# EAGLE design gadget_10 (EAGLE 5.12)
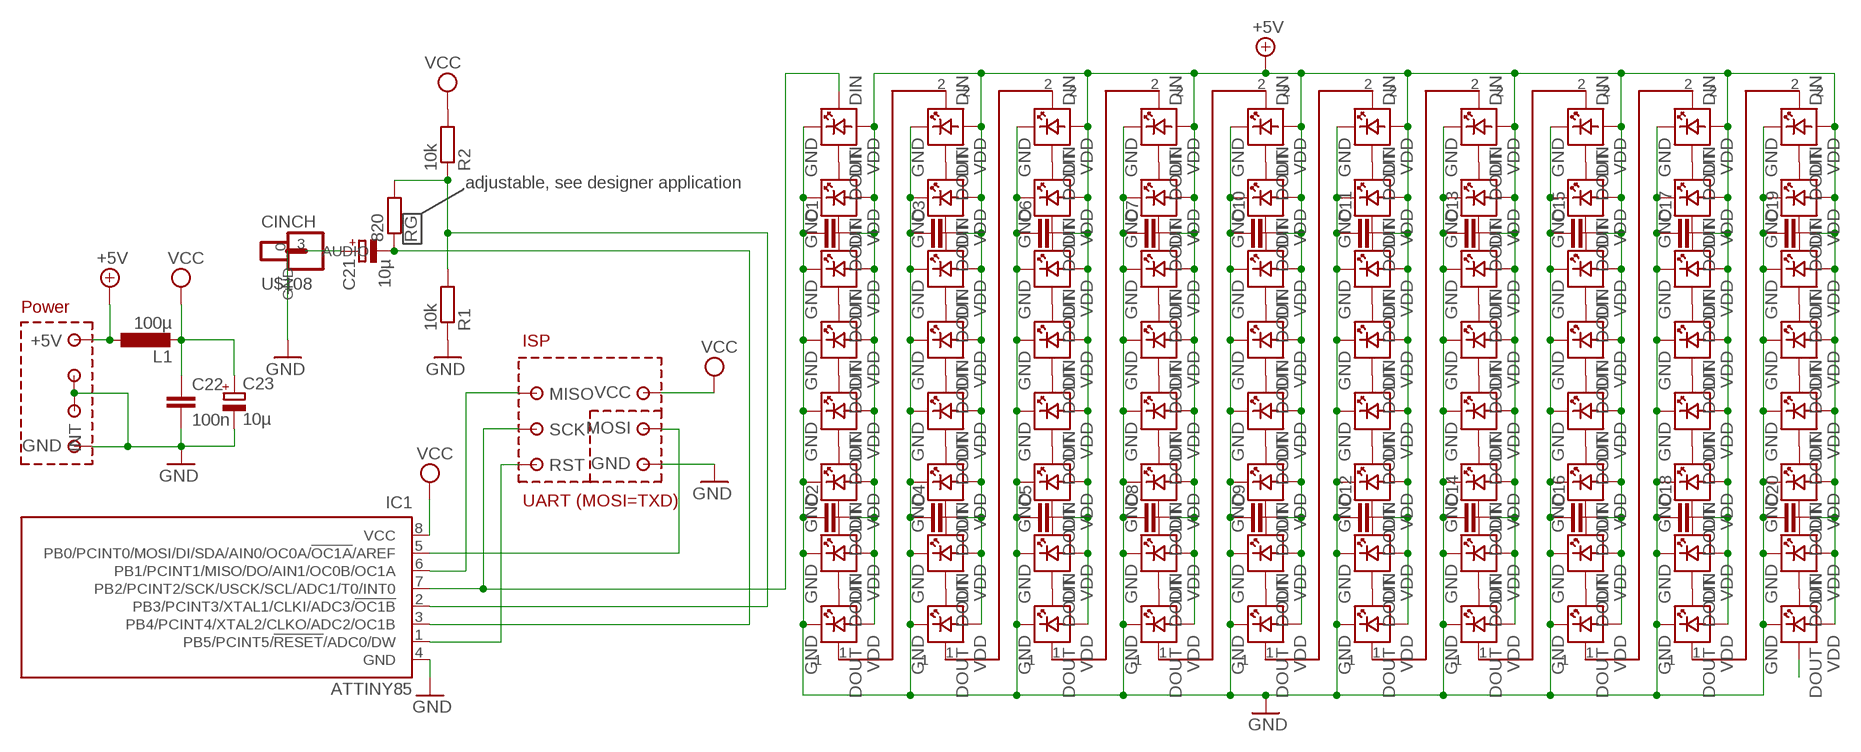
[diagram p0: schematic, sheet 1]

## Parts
C1  C-EU050-024X044  [C050-024X044]
C2  C-EU050-024X044  [C050-024X044]
C3  C-EU050-024X044  [C050-024X044]
C4  C-EU050-024X044  [C050-024X044]
C5  C-EU050-024X044  [C050-024X044]
C6  C-EU050-024X044  [C050-024X044]
C7  C-EU050-024X044  [C050-024X044]
C8  C-EU050-024X044  [C050-024X044]
C9  C-EU050-024X044  [C050-024X044]
C10  C-EU050-024X044  [C050-024X044]
C11  C-EU050-024X044  [C050-024X044]
C12  C-EU050-024X044  [C050-024X044]
C13  C-EU050-024X044  [C050-024X044]
C14  C-EU050-024X044  [C050-024X044]
C15  C-EU050-024X044  [C050-024X044]
C16  C-EU050-024X044  [C050-024X044]
C17  C-EU050-024X044  [C050-024X044]
C18  C-EU050-024X044  [C050-024X044]
C19  C-EU050-024X044  [C050-024X044]
C20  C-EU050-024X044  [C050-024X044]
C21  10µ  CPOL-EUE2.5-5  [E2,5-5]
C22  100n  C-EU025-024X044  [C025-024X044]
C23  10µ  CPOL-EUE2.5-5  [E2,5-5]
IC1  ATTINY85  TINY25/45/85  [DIL08]
L1  100µ  L-EU0207/12  [0207/12]
R1  10k  R-EU_0207/10  [0207/10]
R2  10k  R-EU_0207/7  [0207/7]
RG  820  R-EU_0207/7  [0207/7]
U$1  SPECIAL01  [SPECIAL01]
U$2  SPECIAL01  [SPECIAL01]
U$3  SPECIAL01  [SPECIAL01]
U$4  SPECIAL01  [SPECIAL01]
U$5  SPECIAL01  [SPECIAL01]
U$6  SPECIAL01  [SPECIAL01]
U$7  SPECIAL01  [SPECIAL01]
U$8  WS2812B  [WS2812B]
U$9  WS2812B  [WS2812B]
U$10  WS2812B  [WS2812B]
U$11  WS2812B  [WS2812B]
U$12  WS2812B  [WS2812B]
U$13  WS2812B  [WS2812B]
U$14  WS2812B  [WS2812B]
U$15  WS2812B  [WS2812B]
U$16  WS2812B  [WS2812B]
U$17  WS2812B  [WS2812B]
U$18  WS2812B  [WS2812B]
U$19  WS2812B  [WS2812B]
U$20  WS2812B  [WS2812B]
U$21  WS2812B  [WS2812B]
U$22  WS2812B  [WS2812B]
U$23  WS2812B  [WS2812B]
U$24  WS2812B  [WS2812B]
U$25  WS2812B  [WS2812B]
U$26  WS2812B  [WS2812B]
U$27  WS2812B  [WS2812B]
U$28  WS2812B  [WS2812B]
U$29  WS2812B  [WS2812B]
U$30  WS2812B  [WS2812B]
U$31  WS2812B  [WS2812B]
U$32  WS2812B  [WS2812B]
U$33  WS2812B  [WS2812B]
U$34  WS2812B  [WS2812B]
U$35  WS2812B  [WS2812B]
U$36  WS2812B  [WS2812B]
U$37  WS2812B  [WS2812B]
U$38  WS2812B  [WS2812B]
U$39  WS2812B  [WS2812B]
U$40  WS2812B  [WS2812B]
U$41  WS2812B  [WS2812B]
U$42  WS2812B  [WS2812B]
U$43  WS2812B  [WS2812B]
U$44  WS2812B  [WS2812B]
U$45  WS2812B  [WS2812B]
U$46  WS2812B  [WS2812B]
U$47  WS2812B  [WS2812B]
U$48  WS2812B  [WS2812B]
U$49  WS2812B  [WS2812B]
U$50  WS2812B  [WS2812B]
U$51  WS2812B  [WS2812B]
U$52  WS2812B  [WS2812B]
U$53  WS2812B  [WS2812B]
U$54  WS2812B  [WS2812B]
U$55  WS2812B  [WS2812B]
U$56  WS2812B  [WS2812B]
U$57  WS2812B  [WS2812B]
U$58  WS2812B  [WS2812B]
U$59  WS2812B  [WS2812B]
U$60  WS2812B  [WS2812B]
U$61  WS2812B  [WS2812B]
U$62  WS2812B  [WS2812B]
U$63  WS2812B  [WS2812B]
U$64  WS2812B  [WS2812B]
U$65  WS2812B  [WS2812B]
U$66  WS2812B  [WS2812B]
U$67  WS2812B  [WS2812B]
U$68  WS2812B  [WS2812B]
U$69  WS2812B  [WS2812B]
U$70  WS2812B  [WS2812B]
U$71  WS2812B  [WS2812B]
U$72  WS2812B  [WS2812B]
U$73  WS2812B  [WS2812B]
U$74  WS2812B  [WS2812B]
U$75  WS2812B  [WS2812B]
U$76  WS2812B  [WS2812B]
U$77  WS2812B  [WS2812B]
U$78  WS2812B  [WS2812B]
U$79  WS2812B  [WS2812B]
U$80  WS2812B  [WS2812B]
U$81  WS2812B  [WS2812B]
U$82  WS2812B  [WS2812B]
U$83  WS2812B  [WS2812B]
U$84  WS2812B  [WS2812B]
U$85  WS2812B  [WS2812B]
U$86  WS2812B  [WS2812B]
U$87  WS2812B  [WS2812B]
U$88  SPECIAL01  [SPECIAL01]
U$89  SPECIAL01  [SPECIAL01]
U$90  MOSI  PAD  [PAD]
U$91  MISO  PAD  [PAD]
U$92  SCK  PAD  [PAD]
U$93  RST  PAD  [PAD]
U$94  VCC  PAD  [PAD]
U$95  GND  PAD  [PAD]
U$96  GND  PAD  [PAD]
U$97  INT  PAD  [PAD]
U$98  PAD  [PAD]
U$108  CINCH  [CINCH]
VOLPWM_VCC1  +5V  PAD  [PAD]

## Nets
+5V: C1.2 C2.2 C3.2 C4.2 C5.2 C6.2 C7.2 C8.2 C9.2 C10.2 C11.2 C12.2 C13.2 C14.2 C15.2 C16.2 C17.2 C18.2 C19.2 C20.2 L1.1 U$8.1(VDD) U$9.1(VDD) U$10.1(VDD) U$11.1(VDD) U$12.1(VDD) U$13.1(VDD) U$14.1(VDD) U$15.1(VDD) U$16.1(VDD) U$17.1(VDD) U$18.1(VDD) U$19.1(VDD) U$20.1(VDD) U$21.1(VDD) U$22.1(VDD) U$23.1(VDD) U$24.1(VDD) U$25.1(VDD) U$26.1(VDD) U$27.1(VDD) U$28.1(VDD) U$29.1(VDD) U$30.1(VDD) U$31.1(VDD) U$32.1(VDD) U$33.1(VDD) U$34.1(VDD) U$35.1(VDD) U$36.1(VDD) U$37.1(VDD) U$38.1(VDD) U$39.1(VDD) U$40.1(VDD) U$41.1(VDD) U$42.1(VDD) U$43.1(VDD) U$44.1(VDD) U$45.1(VDD) U$46.1(VDD) U$47.1(VDD) U$48.1(VDD) U$49.1(VDD) U$50.1(VDD) U$51.1(VDD) U$52.1(VDD) U$53.1(VDD) U$54.1(VDD) U$55.1(VDD) U$56.1(VDD) U$57.1(VDD) U$58.1(VDD) U$59.1(VDD) U$60.1(VDD) U$61.1(VDD) U$62.1(VDD) U$63.1(VDD) U$64.1(VDD) U$65.1(VDD) U$66.1(VDD) U$67.1(VDD) U$68.1(VDD) U$69.1(VDD) U$70.1(VDD) U$71.1(VDD) U$72.1(VDD) U$73.1(VDD) U$74.1(VDD) U$75.1(VDD) U$76.1(VDD) U$77.1(VDD) U$78.1(VDD) U$79.1(VDD) U$80.1(VDD) U$81.1(VDD) U$82.1(VDD) U$83.1(VDD) U$84.1(VDD) U$85.1(VDD) U$86.1(VDD) U$87.1(VDD) VOLPWM_VCC1.P$1
GND: C1.1 C2.1 C3.1 C4.1 C5.1 C6.1 C7.1 C8.1 C9.1 C10.1 C11.1 C12.1 C13.1 C14.1 C15.1 C16.1 C17.1 C18.1 C19.1 C20.1 C22.2 C23.- IC1.4(GND) R1.1 U$8.3(GND) U$9.3(GND) U$10.3(GND) U$11.3(GND) U$12.3(GND) U$13.3(GND) U$14.3(GND) U$15.3(GND) U$16.3(GND) U$17.3(GND) U$18.3(GND) U$19.3(GND) U$20.3(GND) U$21.3(GND) U$22.3(GND) U$23.3(GND) U$24.3(GND) U$25.3(GND) U$26.3(GND) U$27.3(GND) U$28.3(GND) U$29.3(GND) U$30.3(GND) U$31.3(GND) U$32.3(GND) U$33.3(GND) U$34.3(GND) U$35.3(GND) U$36.3(GND) U$37.3(GND) U$38.3(GND) U$39.3(GND) U$40.3(GND) U$41.3(GND) U$42.3(GND) U$43.3(GND) U$44.3(GND) U$45.3(GND) U$46.3(GND) U$47.3(GND) U$48.3(GND) U$49.3(GND) U$50.3(GND) U$51.3(GND) U$52.3(GND) U$53.3(GND) U$54.3(GND) U$55.3(GND) U$56.3(GND) U$57.3(GND) U$58.3(GND) U$59.3(GND) U$60.3(GND) U$61.3(GND) U$62.3(GND) U$63.3(GND) U$64.3(GND) U$65.3(GND) U$66.3(GND) U$67.3(GND) U$68.3(GND) U$69.3(GND) U$70.3(GND) U$71.3(GND) U$72.3(GND) U$73.3(GND) U$74.3(GND) U$75.3(GND) U$76.3(GND) U$77.3(GND) U$78.3(GND) U$79.3(GND) U$80.3(GND) U$81.3(GND) U$82.3(GND) U$83.3(GND) U$84.3(GND) U$85.3(GND) U$86.3(GND) U$87.3(GND) U$95.P$1 U$96.P$1 U$97.P$1 U$98.P$1 U$108.0(GND)
N$1: U$1.1 U$15.2(DOUT)
N$4: U$1.2 U$16.4(DIN)
N$5: U$8.2(DOUT) U$9.4(DIN)
N$6: U$2.1 U$23.2(DOUT)
N$7: U$2.2 U$24.4(DIN)
N$8: U$3.1 U$31.2(DOUT)
N$9: U$9.2(DOUT) U$10.4(DIN)
N$10: U$10.2(DOUT) U$11.4(DIN)
N$11: U$11.2(DOUT) U$12.4(DIN)
N$12: U$12.2(DOUT) U$13.4(DIN)
N$13: U$13.2(DOUT) U$14.4(DIN)
N$14: U$14.2(DOUT) U$15.4(DIN)
N$15: U$16.2(DOUT) U$17.4(DIN)
N$16: U$17.2(DOUT) U$18.4(DIN)
N$17: U$18.2(DOUT) U$19.4(DIN)
N$18: U$19.2(DOUT) U$20.4(DIN)
N$19: U$20.2(DOUT) U$21.4(DIN)
N$20: U$21.2(DOUT) U$22.4(DIN)
N$21: U$22.2(DOUT) U$23.4(DIN)
N$22: U$24.2(DOUT) U$25.4(DIN)
N$23: U$25.2(DOUT) U$26.4(DIN)
N$24: U$26.2(DOUT) U$27.4(DIN)
N$25: U$27.2(DOUT) U$28.4(DIN)
N$26: U$28.2(DOUT) U$29.4(DIN)
N$27: U$29.2(DOUT) U$30.4(DIN)
N$28: U$30.2(DOUT) U$31.4(DIN)
N$29: U$32.2(DOUT) U$33.4(DIN)
N$30: U$33.2(DOUT) U$34.4(DIN)
N$31: U$34.2(DOUT) U$35.4(DIN)
N$32: U$35.2(DOUT) U$36.4(DIN)
N$33: U$36.2(DOUT) U$37.4(DIN)
N$34: U$37.2(DOUT) U$38.4(DIN)
N$35: U$38.2(DOUT) U$39.4(DIN)
N$36: U$40.2(DOUT) U$41.4(DIN)
N$37: U$41.2(DOUT) U$42.4(DIN)
N$38: U$42.2(DOUT) U$43.4(DIN)
N$39: U$43.2(DOUT) U$44.4(DIN)
N$40: U$44.2(DOUT) U$45.4(DIN)
N$41: U$45.2(DOUT) U$46.4(DIN)
N$42: U$46.2(DOUT) U$47.4(DIN)
N$43: U$48.2(DOUT) U$49.4(DIN)
N$44: U$49.2(DOUT) U$50.4(DIN)
N$45: U$50.2(DOUT) U$51.4(DIN)
N$46: U$51.2(DOUT) U$52.4(DIN)
N$47: U$52.2(DOUT) U$53.4(DIN)
N$48: U$53.2(DOUT) U$54.4(DIN)
N$49: U$54.2(DOUT) U$55.4(DIN)
N$50: U$56.2(DOUT) U$57.4(DIN)
N$51: U$57.2(DOUT) U$58.4(DIN)
N$52: U$58.2(DOUT) U$59.4(DIN)
N$53: U$59.2(DOUT) U$60.4(DIN)
N$54: U$60.2(DOUT) U$61.4(DIN)
N$55: U$61.2(DOUT) U$62.4(DIN)
N$56: U$62.2(DOUT) U$63.4(DIN)
N$57: U$64.2(DOUT) U$65.4(DIN)
N$58: U$65.2(DOUT) U$66.4(DIN)
N$59: U$66.2(DOUT) U$67.4(DIN)
N$60: U$67.2(DOUT) U$68.4(DIN)
N$61: U$68.2(DOUT) U$69.4(DIN)
N$62: U$69.2(DOUT) U$70.4(DIN)
N$63: U$70.2(DOUT) U$71.4(DIN)
N$64: U$72.2(DOUT) U$73.4(DIN)
N$65: U$73.2(DOUT) U$74.4(DIN)
N$66: U$74.2(DOUT) U$75.4(DIN)
N$67: U$75.2(DOUT) U$76.4(DIN)
N$68: U$76.2(DOUT) U$77.4(DIN)
N$69: U$77.2(DOUT) U$78.4(DIN)
N$70: U$78.2(DOUT) U$79.4(DIN)
N$71: U$80.2(DOUT) U$81.4(DIN)
N$72: U$81.2(DOUT) U$82.4(DIN)
N$73: U$82.2(DOUT) U$83.4(DIN)
N$74: U$83.2(DOUT) U$84.4(DIN)
N$75: U$84.2(DOUT) U$85.4(DIN)
N$76: U$85.2(DOUT) U$86.4(DIN)
N$77: U$86.2(DOUT) U$87.4(DIN)
N$78: U$3.2 U$32.4(DIN)
N$79: U$4.1 U$39.2(DOUT)
N$80: U$4.2 U$40.4(DIN)
N$81: U$5.1 U$47.2(DOUT)
N$82: U$5.2 U$48.4(DIN)
N$83: U$6.1 U$55.2(DOUT)
N$84: U$6.2 U$56.4(DIN)
N$85: U$7.1 U$63.2(DOUT)
N$86: U$7.2 U$64.4(DIN)
N$87: U$71.2(DOUT) U$88.1
N$88: U$72.4(DIN) U$88.2
N$89: U$79.2(DOUT) U$89.1
N$90: U$80.4(DIN) U$89.2
N$98: C21.+ U$108.3(AUDIO)
N$111: U$87.2(DOUT)
N$112: C21.- IC1.3(PB4/PCINT4/XTAL2/CLKO/ADC2/OC1B) RG.1
N$113: IC1.2(PB3/PCINT3/XTAL1/CLKI/ADC3/!OC1B!) R1.2 R2.1 RG.2
N$115: IC1.1(PB5/PCINT5/!RESET!/ADC0/DW) U$93.P$1
N$116: IC1.7(PB2/PCINT2/SCK/USCK/SCL/ADC1/T0/INT0) U$8.4(DIN) U$92.P$1
N$117: IC1.5(PB0/PCINT0/MOSI/DI/SDA/AIN0/OC0A/!OC1A!/AREF) U$90.P$1
N$118: IC1.6(PB1/PCINT1/MISO/DO/AIN1/OC0B/OC1A) U$91.P$1
VCC: C22.1 C23.+ IC1.8(VCC) L1.2 R2.2 U$94.P$1

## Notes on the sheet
- adjustable, see designer application
- Power
- ISP
- UART (MOSI=TXD)

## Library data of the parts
C1-C20 C22 = rcl:C-EU: CAPACITOR, European symbol
C21 C23 = rcl:CPOL-EU: POLARIZED CAPACITOR, European symbol
IC1 = atmel:TINY25/45/85
L1 = rcl:L-EU: INDUCTOR, European symbol
R1 R2 RG = rcl:R-EU_: RESISTOR, European symbol
U$1-U$7 U$88 U$89 = jumper:SPECIAL01
U$8-U$87 = led:WS2812B
U$90-U$98 VOLPWM_VCC1 = jumper:PAD
U$108 = jumper:CINCH

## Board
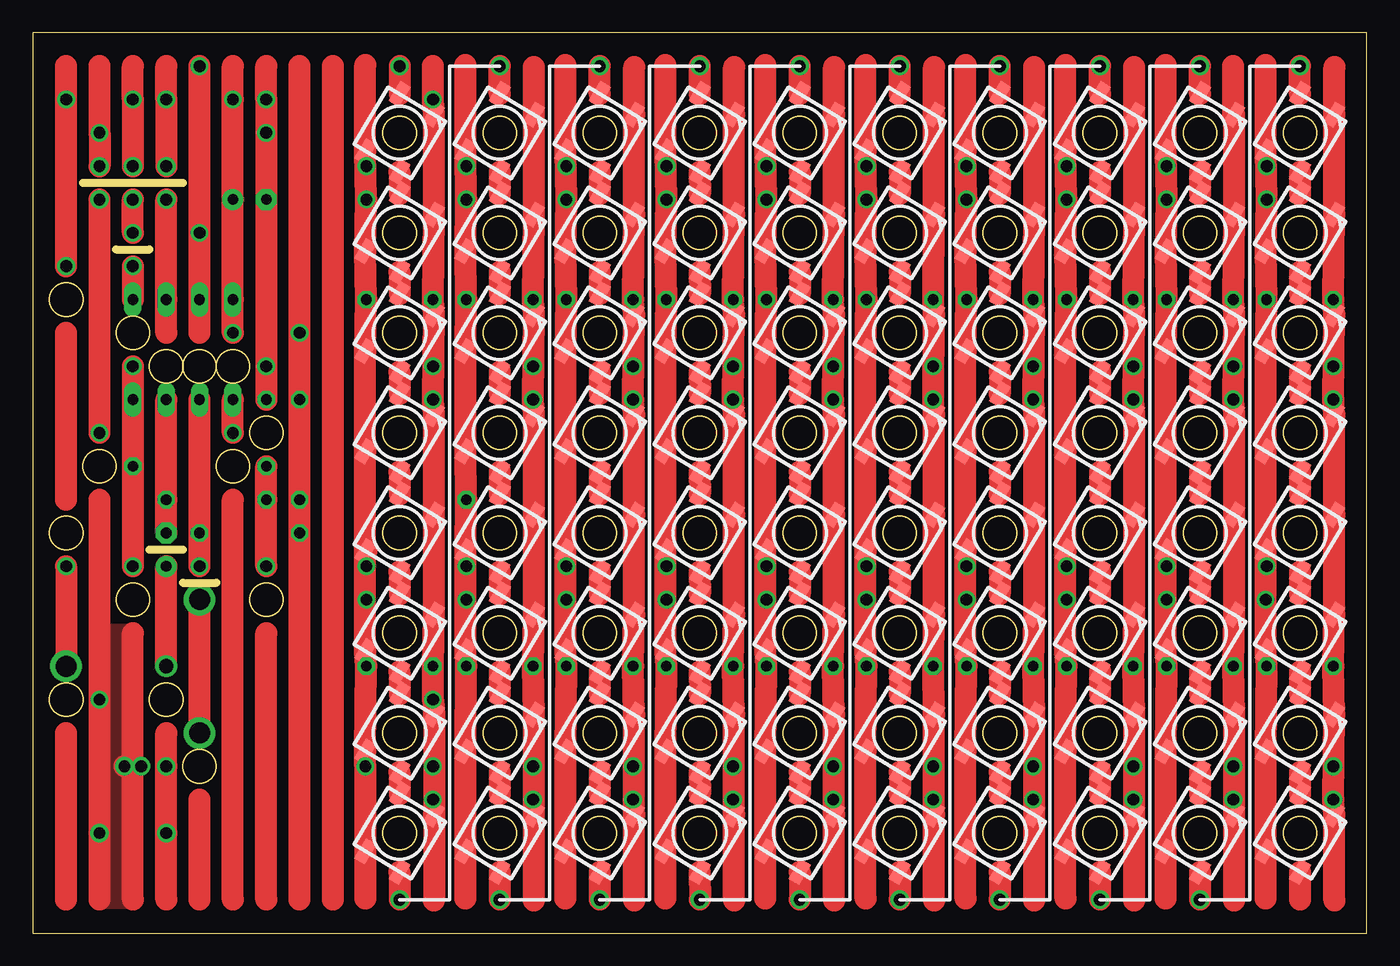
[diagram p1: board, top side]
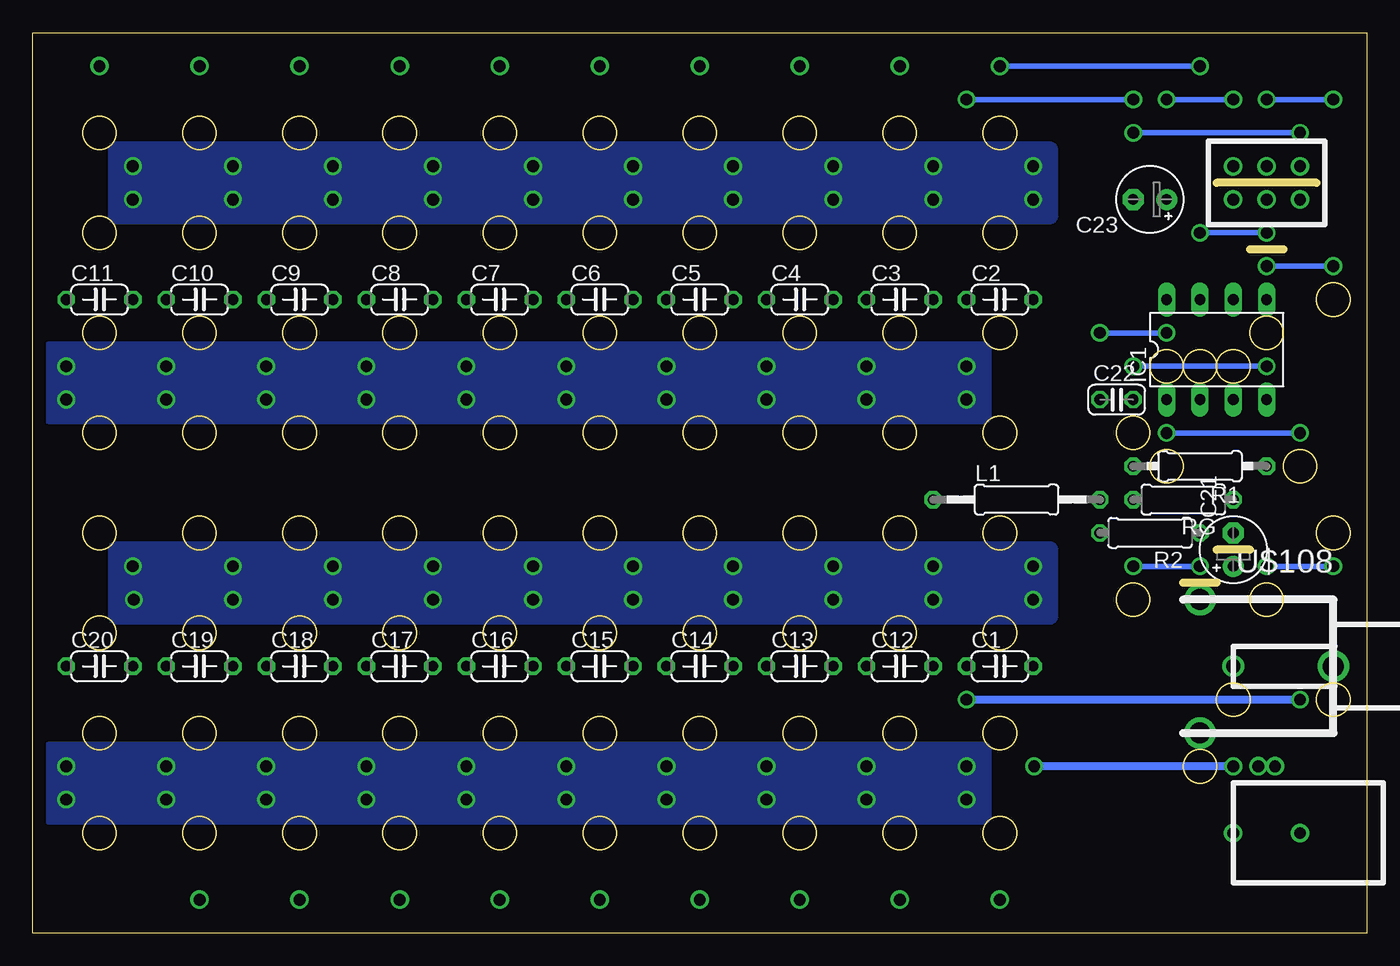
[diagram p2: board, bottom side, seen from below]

Size 101.6 x 68.58 mm. Coordinates in mm from the lower left corner, seen from the top.
Outline: 0,0 101.6,0 101.6,68.58 0,68.58 0,0
Copper layers (1*16): Top 0.035mm / dielectric 1.5mm / Bottom 0.035mm
Design rules "default": minimum track width 10mil, minimum drill 24mil, track to track 8mil, track to pad 8mil, pad to pad 8mil, via to via 8mil, smd to smd 8mil, copper to edge 40mil, drill to drill 8mil, minimum pad ring 10mil, minimum via ring 8mil, stop-mask expansion 4mil, vias tented up to drill 0mil, thermal gap 10mil
Milling: area 26.7,59.7 to 29.2,62.2; area 34.3,59.7 to 36.8,62.2; area 41.9,59.7 to 44.5,62.2; area 49.5,59.7 to 52.1,62.2; area 57.1,59.7 to 59.7,62.2; area 64.8,59.7 to 67.3,62.2; area 72.4,59.7 to 74.9,62.2; area 80,59.7 to 82.5,62.2; area 87.6,59.7 to 90.2,62.2; area 95.2,59.7 to 97.8,62.2; area 26.7,14 to 29.2,16.5; area 34.3,14 to 36.8,16.5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; 4 lines

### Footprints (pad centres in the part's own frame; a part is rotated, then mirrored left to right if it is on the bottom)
C050-024X044 = drill 0.813 octagon: 1 -2.54,0; 2 2.54,0
E2,5-5 = drill 0.813 pad 1.6 round: + -1.27,0 | drill 0.813 pad 1.6 octagon: - 1.27,0
C025-024X044 = drill 0.813 octagon: 1 -1.27,0; 2 1.27,0
DIL08 = drill 0.813 long: 1 -3.81,-3.81; 2 -1.27,-3.81; 3 1.27,-3.81; 4 3.81,-3.81; 5 3.81,3.81; 6 1.27,3.81; 7 -1.27,3.81; 8 -3.81,3.81
0207/12 = drill 0.813 octagon: 1 -6.35,0; 2 6.35,0
0207/10 = drill 0.813 octagon: 1 -5.08,0; 2 5.08,0
0207/7 = drill 0.813 octagon: 1 -3.81,0; 2 3.81,0
SPECIAL01 = drill 0.9 round: 1 -3.81,-31.75; 2 3.81,31.75
WS2812B = smd 1.778 x 0.914: 1 -2.54,1.524; 2 -2.54,-1.524; 3 2.54,-1.524; 4 2.54,1.524
PAD = drill 0.9 round: P$1 0,0
CINCH = drill 1.6 round: 0 0,0; 1 10.16,5.08; 2 10.16,-5.08 | drill 1.1 round: 3 7.62,0

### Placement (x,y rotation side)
C1  27.94,20.32 0 bottom
C2  27.94,48.26 0 bottom
C3  35.56,48.26 0 bottom
C4  43.18,48.26 0 bottom
C5  50.8,48.26 0 bottom
C6  58.42,48.26 0 bottom
C7  66.04,48.26 0 bottom
C8  73.66,48.26 0 bottom
C9  81.28,48.26 0 bottom
C10  88.9,48.26 0 bottom
C11  96.52,48.26 0 bottom
C12  35.56,20.32 0 bottom
C13  43.18,20.32 0 bottom
C14  50.8,20.32 0 bottom
C15  58.42,20.32 0 bottom
C16  66.04,20.32 0 bottom
C17  73.66,20.32 0 bottom
C18  81.28,20.32 0 bottom
C19  88.9,20.32 0 bottom
C20  96.52,20.32 0 bottom
C21  10.16,29.21 90 bottom
C22  19.05,40.64 0 bottom
C23  16.51,55.88 180 bottom
IC1  11.43,44.45 0 bottom
L1  26.67,33.02 0 bottom
R1  12.7,35.56 180 bottom
R2  16.51,30.48 180 bottom
RG  13.97,33.02 180 bottom
U$1  31.75,34.29 0 top
U$2  39.37,34.29 0 top
U$3  46.99,34.29 0 top
U$4  54.61,34.29 0 top
U$5  62.23,34.29 0 top
U$6  69.85,34.29 0 top
U$7  77.47,34.29 0 top
U$8  27.94,60.96 59 top
U$9  27.94,53.34 59 top
U$10  27.94,45.72 59 top
U$11  27.94,38.1 59 top
U$12  27.94,30.48 59 top
U$13  27.94,22.86 59 top
U$14  27.94,15.24 59 top
U$15  27.94,7.62 59 top
U$16  35.56,60.96 59 top
U$17  35.56,53.34 59 top
U$18  35.56,45.72 59 top
U$19  35.56,38.1 59 top
U$20  35.56,30.48 59 top
U$21  35.56,22.86 59 top
U$22  35.56,15.24 59 top
U$23  35.56,7.62 59 top
U$24  43.18,60.96 59 top
U$25  43.18,53.34 59 top
U$26  43.18,45.72 59 top
U$27  43.18,38.1 59 top
U$28  43.18,30.48 59 top
U$29  43.18,22.86 59 top
U$30  43.18,15.24 59 top
U$31  43.18,7.62 59 top
U$32  50.8,60.96 59 top
U$33  50.8,53.34 59 top
U$34  50.8,45.72 59 top
U$35  50.8,38.1 59 top
U$36  50.8,30.48 59 top
U$37  50.8,22.86 59 top
U$38  50.8,15.24 59 top
U$39  50.8,7.62 59 top
U$40  58.42,60.96 59 top
U$41  58.42,53.34 59 top
U$42  58.42,45.72 59 top
U$43  58.42,38.1 59 top
U$44  58.42,30.48 59 top
U$45  58.42,22.86 59 top
U$46  58.42,15.24 59 top
U$47  58.42,7.62 59 top
U$48  66.04,60.96 59 top
U$49  66.04,53.34 59 top
U$50  66.04,45.72 59 top
U$51  66.04,38.1 59 top
U$52  66.04,30.48 59 top
U$53  66.04,22.86 59 top
U$54  66.04,15.24 59 top
U$55  66.04,7.62 59 top
U$56  73.66,60.96 59 top
U$57  73.66,53.34 59 top
U$58  73.66,45.72 59 top
U$59  73.66,38.1 59 top
U$60  73.66,30.48 59 top
U$61  73.66,22.86 59 top
U$62  73.66,15.24 59 top
U$63  73.66,7.62 59 top
U$64  81.28,60.96 59 top
U$65  81.28,53.34 59 top
U$66  81.28,45.72 59 top
U$67  81.28,38.1 59 top
U$68  81.28,30.48 59 top
U$69  81.28,22.86 59 top
U$70  81.28,15.24 59 top
U$71  81.28,7.62 59 top
U$72  88.9,60.96 59 top
U$73  88.9,53.34 59 top
U$74  88.9,45.72 59 top
U$75  88.9,38.1 59 top
U$76  88.9,30.48 59 top
U$77  88.9,22.86 59 top
U$78  88.9,15.24 59 top
U$79  88.9,7.62 59 top
U$80  96.52,60.96 59 top
U$81  96.52,53.34 59 top
U$82  96.52,45.72 59 top
U$83  96.52,38.1 59 top
U$84  96.52,30.48 59 top
U$85  96.52,22.86 59 top
U$86  96.52,15.24 59 top
U$87  96.52,7.62 59 top
U$88  85.09,34.29 0 top
U$89  92.71,34.29 0 top
U$90  7.62,58.42 90 bottom
U$91  10.16,55.88 270 bottom
U$92  7.62,55.88 270 bottom
U$93  5.08,55.88 270 bottom
U$94  10.16,58.42 90 bottom
U$95  5.08,58.42 90 bottom
U$96  5.08,7.62 180 bottom
U$97  8.26,12.7 270 bottom
U$98  6.99,12.7 0 bottom
U$108  2.54,20.32 180 bottom
VOLPWM_VCC1  10.16,7.62 180 bottom

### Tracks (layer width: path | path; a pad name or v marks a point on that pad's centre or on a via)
+5V  (via drill 0.9)
  Top 1.676: U$12.1 U$13.1 C1.2 U$14.1 v25.32,12.7 U$15.1 25.32,2.62 | 32.95,2.62 U$23.1 U$22.1 C12.2 U$21.1 U$20.1 L1.1 U$19.1 U$18.1 C3.2 U$17.1 v33.02,55.88 U$16.1 32.95,66.11 | 40.56,2.62 U$31.1 U$30.1 C13.2 U$29.1 U$28.1 U$27.1 U$26.1 C4.2 U$25.1 v40.64,55.88 U$24.1 40.56,66.11 | 48.19,2.62 U$39.1 U$38.1 C14.2 U$37.1 U$36.1 U$35.1 U$34.1 C5.2 U$33.1 v48.26,55.88 U$32.1 48.19,66.11 | 55.8,2.62 U$47.1 U$46.1 C15.2 U$45.1 U$44.1 U$43.1 U$42.1 C6.2 U$41.1 v55.88,55.88 U$40.1 55.8,66.11 | 63.42,2.62 U$55.1 U$54.1 C16.2 U$53.1 U$52.1 U$51.1 U$50.1 C7.2 U$49.1 v63.5,55.88 U$48.1 63.42,66.11 | 71.05,2.62 U$63.1 U$62.1 C17.2 U$61.1 U$60.1 U$59.1 U$58.1 C8.2 U$57.1 v71.12,55.88 U$56.1 71.05,66.11 | 78.67,2.62 U$71.1 U$70.1 C18.2 U$69.1 U$68.1 U$67.1 U$66.1 C9.2 U$65.1 v78.74,55.88 U$64.1 78.67,66.11 | 86.28,2.62 U$79.1 U$78.1 C19.2 U$77.1 U$76.1 U$75.1 U$74.1 C10.2 U$73.1 v86.36,55.88 U$72.1 86.28,66.11 | 93.91,2.62 U$87.1 U$86.1 C20.2 U$85.1 v93.91,25.4 U$84.1 U$83.1 U$82.1 C11.2 U$81.1 v93.98,55.88 U$80.1 93.91,66.11 | 25.32,66.11 U$8.1 v25.4,55.88 U$9.1 C2.2 U$10.1 U$11.1 U$12.1 | 10.16,2.54 VOLPWM_VCC1.P$1 v10.16,12.7 10.16,15.24 | U$12.1 25.4,29.09
  Bottom 0.61: v10.16,12.7 v25.32,12.7
  other vias: 86.36,25.4 78.74,25.4 71.12,25.4 63.5,25.4 55.88,25.4 48.26,25.4 40.64,25.4 33.02,25.4 25.4,25.4 25.4,58.42 33.02,58.42 40.64,58.42 48.26,58.42 55.88,58.42 63.5,58.42 71.12,58.42 78.74,58.42 86.36,58.42 93.98,58.42 25.4,27.94 33.02,27.94 40.64,27.94 48.26,27.94 55.88,27.94 63.5,27.94 71.12,27.94 78.74,27.94 86.36,27.94 93.98,27.94
  pour Bottom (no thermals): 24.13,59.69 95.25,59.69 95.25,54.61 24.13,54.61
  pour Bottom (no thermals): 24.13,29.21 95.25,29.21 95.25,24.13 24.13,24.13
GND  (via drill 0.9)
  Top 1.676: v7.62,43.18 IC1.4 R1.1 v7.62,27.94 | 30.55,2.47 U$15.3 U$14.3 v30.48,17.78 C1.1 U$13.3 U$12.3 U$11.3 v30.48,40.64 U$10.3 C2.1 U$9.3 U$8.3 v30.48,63.5 30.48,66.04 | 38.17,2.47 U$23.3 U$22.3 C12.1 U$21.3 U$20.3 U$19.3 v38.1,40.64 U$18.3 C3.1 U$17.3 U$16.3 38.17,65.97 | 45.79,2.47 U$31.3 U$30.3 C13.1 U$29.3 U$28.3 U$27.3 v45.72,40.64 U$26.3 C4.1 U$25.3 U$24.3 45.79,65.97 | 53.41,2.47 U$39.3 U$38.3 C14.1 U$37.3 U$36.3 U$35.3 v53.34,40.64 U$34.3 C5.1 U$33.3 U$32.3 53.41,65.97 | 61.03,2.47 U$47.3 U$46.3 C15.1 U$45.3 U$44.3 U$43.3 v60.96,40.64 U$42.3 C6.1 U$41.3 U$40.3 61.03,65.97 | 68.65,2.47 U$55.3 U$54.3 C16.1 U$53.3 U$52.3 U$51.3 v68.58,40.64 U$50.3 C7.1 U$49.3 U$48.3 68.65,65.97 | 76.28,2.47 U$63.3 U$62.3 C17.1 U$61.3 U$60.3 U$59.3 v76.2,40.64 U$58.3 C8.1 U$57.3 U$56.3 76.28,65.97 | 83.89,2.47 U$71.3 U$70.3 C18.1 U$69.3 U$68.3 U$67.3 v83.82,40.64 U$66.3 C9.1 U$65.3 U$64.3 83.89,65.97 | 91.51,2.47 U$79.3 U$78.3 C19.1 U$77.3 U$76.3 U$75.3 v91.44,40.64 U$74.3 C10.1 U$73.3 U$72.3 91.44,62.35 91.44,66.04 | 99.14,2.47 U$87.3 v99.06,10.16 U$86.3 C20.1 U$85.3 U$84.3 U$83.3 v99.06,40.64 U$82.3 C11.1 U$81.3 U$80.3 99.14,65.97 | C22.2 v17.78,43.18 C23.- v17.78,60.96 v17.78,63.5 17.78,66.04 | 5.08,2.54 U$96.P$1 v5.08,17.78 5.08,33.02 | 7.62,12.7 U$98.P$1 | 7.62,2.54 7.62,12.7 | 7.62,12.7 7.62,22.86 | v2.54,27.94 U$108.0 | U$95.P$1 v5.08,60.96 5.08,66.04
  Bottom 0.406: v17.78,43.18 v7.62,43.18 | v30.48,63.5 v17.78,63.5 | v7.62,27.94 v2.54,27.94 | v17.78,60.96 v5.08,60.96
  Bottom 0.61: v5.08,17.78 v30.48,17.78
  other vias: 91.44,10.16 83.82,10.16 76.2,10.16 68.58,10.16 60.96,10.16 53.34,10.16 45.72,10.16 38.1,10.16 30.48,10.16 30.48,12.7 38.1,12.7 45.72,12.7 53.34,12.7 60.96,12.7 68.58,12.7 76.2,12.7 83.82,12.7 91.44,12.7 99.06,12.7 30.48,43.18 38.1,43.18 45.72,43.18 53.34,43.18 60.96,43.18 68.58,43.18 76.2,43.18 83.82,43.18 91.44,43.18 99.06,43.18
  pour Bottom (no thermals): 29.21,44.45 100.33,44.45 100.33,39.37 29.21,39.37
  pour Bottom (no thermals): 29.21,13.97 100.33,13.97 100.33,8.89 29.21,8.89
  pour Top: 5.08,22.86 7.62,22.86 7.62,2.54 5.08,2.54
N$1
  Top 1.676: U$15.2 U$1.1
N$2
  Top 1.676: 2.54,2.54 2.54,15.24
N$3
  Top 1.676: 22.86,2.54 22.86,66.04
N$4
  Top 1.676: U$16.4 U$1.2
N$5
  Top 1.676: U$8.2 U$9.4
N$6
  Top 1.676: U$23.2 U$2.1
N$7
  Top 1.676: U$24.4 U$2.2
N$8
  Top 1.676: U$31.2 U$3.1
N$9
  Top 1.676: U$9.2 U$10.4
N$10
  Top 1.676: U$10.2 U$11.4
N$11
  Top 1.676: U$11.2 U$12.4
N$12
  Top 1.676: U$12.2 U$13.4
N$13
  Top 1.676: U$13.2 U$14.4
N$14
  Top 1.676: U$14.2 U$15.4
N$15
  Top 1.676: U$16.2 U$17.4
N$16
  Top 1.676: U$17.2 U$18.4
N$17
  Top 1.676: U$18.2 U$19.4
N$18
  Top 1.676: U$19.2 U$20.4
N$19
  Top 1.676: U$20.2 U$21.4
N$20
  Top 1.676: U$21.2 U$22.4
N$21
  Top 1.676: U$22.2 U$23.4
N$22
  Top 1.676: U$24.2 U$25.4
N$23
  Top 1.676: U$25.2 U$26.4
N$24
  Top 1.676: U$26.2 U$27.4
N$25
  Top 1.676: U$27.2 U$28.4
N$26
  Top 1.676: U$28.2 U$29.4
N$27
  Top 1.676: U$29.2 U$30.4
N$28
  Top 1.676: U$30.2 U$31.4
N$29
  Top 1.676: U$32.2 U$33.4
N$30
  Top 1.676: U$33.2 U$34.4
N$31
  Top 1.676: U$34.2 U$35.4
N$32
  Top 1.676: U$35.2 U$36.4
N$33
  Top 1.676: U$36.2 U$37.4
N$34
  Top 1.676: U$37.2 U$38.4
N$35
  Top 1.676: U$38.2 U$39.4
N$36
  Top 1.676: U$40.2 U$41.4
N$37
  Top 1.676: U$41.2 U$42.4
N$38
  Top 1.676: U$42.2 U$43.4
N$39
  Top 1.676: U$43.2 U$44.4
N$40
  Top 1.676: U$44.2 U$45.4
N$41
  Top 1.676: U$45.2 U$46.4
N$42
  Top 1.676: U$46.2 U$47.4
N$43
  Top 1.676: U$48.2 U$49.4
N$44
  Top 1.676: U$49.2 U$50.4
N$45
  Top 1.676: U$50.2 U$51.4
N$46
  Top 1.676: U$51.2 U$52.4
N$47
  Top 1.676: U$52.2 U$53.4
N$48
  Top 1.676: U$53.2 U$54.4
N$49
  Top 1.676: U$54.2 U$55.4
N$50
  Top 1.676: U$56.2 U$57.4
N$51
  Top 1.676: U$57.2 U$58.4
N$52
  Top 1.676: U$58.2 U$59.4
N$53
  Top 1.676: U$59.2 U$60.4
N$54
  Top 1.676: U$60.2 U$61.4
N$55
  Top 1.676: U$61.2 U$62.4
N$56
  Top 1.676: U$62.2 U$63.4
N$57
  Top 1.676: U$64.2 U$65.4
N$58
  Top 1.676: U$65.2 U$66.4
N$59
  Top 1.676: U$66.2 U$67.4
N$60
  Top 1.676: U$67.2 U$68.4
N$61
  Top 1.676: U$68.2 U$69.4
N$62
  Top 1.676: U$69.2 U$70.4
N$63
  Top 1.676: U$70.2 U$71.4
N$64
  Top 1.676: U$72.2 U$73.4
N$65
  Top 1.676: U$73.2 U$74.4
N$66
  Top 1.676: U$74.2 U$75.4
N$67
  Top 1.676: U$75.2 U$76.4
N$68
  Top 1.676: U$76.2 U$77.4
N$69
  Top 1.676: U$77.2 U$78.4
N$70
  Top 1.676: U$78.2 U$79.4
N$71
  Top 1.676: U$80.2 U$81.4
N$72
  Top 1.676: U$81.2 U$82.4
N$73
  Top 1.676: U$82.2 U$83.4
N$74
  Top 1.676: U$83.2 U$84.4
N$75
  Top 1.676: U$84.2 U$85.4
N$76
  Top 1.676: U$85.2 U$86.4
N$77
  Top 1.676: U$86.2 U$87.4
N$78
  Top 1.676: U$32.4 U$3.2
N$79
  Top 1.676: U$39.2 U$4.1
N$80
  Top 1.676: U$40.4 U$4.2
N$81
  Top 1.676: U$47.2 U$5.1
N$82
  Top 1.676: U$48.4 U$5.2
N$83
  Top 1.676: U$55.2 U$6.1
N$84
  Top 1.676: U$56.4 U$6.2
N$85
  Top 1.676: U$63.2 U$7.1
N$86
  Top 1.676: U$64.4 U$7.2
N$87
  Top 1.676: U$71.2 U$88.1
N$88
  Top 1.676: U$72.4 U$88.2
N$89
  Top 1.676: U$79.2 U$89.1
N$90
  Top 1.676: U$80.4 U$89.2
N$91
  Top 1.676: 2.54,33.02 2.54,45.72
N$92
  Top 1.676: 15.24,2.54 15.24,33.02
N$93
  Top 1.676: 17.78,2.54 17.78,22.86
N$98
  Top 1.676: U$108.3 C21.+
N$100
  Top 1.676: 12.7,15.24 12.7,25.4
N$102
  Top 1.676: 12.7,2.54 12.7,10.16
N$111
  Top 1.676: U$87.2 96.52,2.54
N$112
  Top 1.676: IC1.3 RG.1 C21.-
N$113  (via drill 0.9)
  Top 1.676: IC1.2 R2.1 v12.7,27.94 | v17.78,27.94 RG.2 R1.2
  Bottom 0.406: v12.7,27.94 v17.78,27.94
N$115  (via drill 0.9)
  Top 1.676: v5.08,38.1 U$93.P$1 | v15.24,38.1 IC1.1
  Bottom 0.406: v5.08,38.1 v15.24,38.1
N$116  (via drill 0.9)
  Top 1.676: 12.7,45.72 IC1.7 v12.7,53.34 v12.7,66.04 | v27.94,66.04 U$8.4 | v7.62,53.34 U$92.P$1
  Bottom 0.406: v12.7,66.04 v27.94,66.04 | v12.7,53.34 v7.62,53.34
N$117  (via drill 0.9)
  Top 1.676: v7.62,50.8 IC1.5 | v2.54,50.8 v2.54,63.5 2.54,66.04 | U$90.P$1 v7.62,63.5 7.62,66.04
  Bottom 0.406: v2.54,50.8 v7.62,50.8 | v2.54,63.5 v7.62,63.5
N$118
  Top 1.676: 10.16,45.72 IC1.6 U$91.P$1
VCC  (via drill 0.9)
  Top 1.676: v15.24,45.72 IC1.8 C23.+ v15.24,63.5 15.24,66.04 | U$94.P$1 v10.16,63.5 10.16,66.04 | 20.32,66.04 v20.32,45.72 C22.1 L1.2 R2.2 20.32,2.54
  Bottom 0.406: v20.32,45.72 v15.24,45.72 | v15.24,63.5 v10.16,63.5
